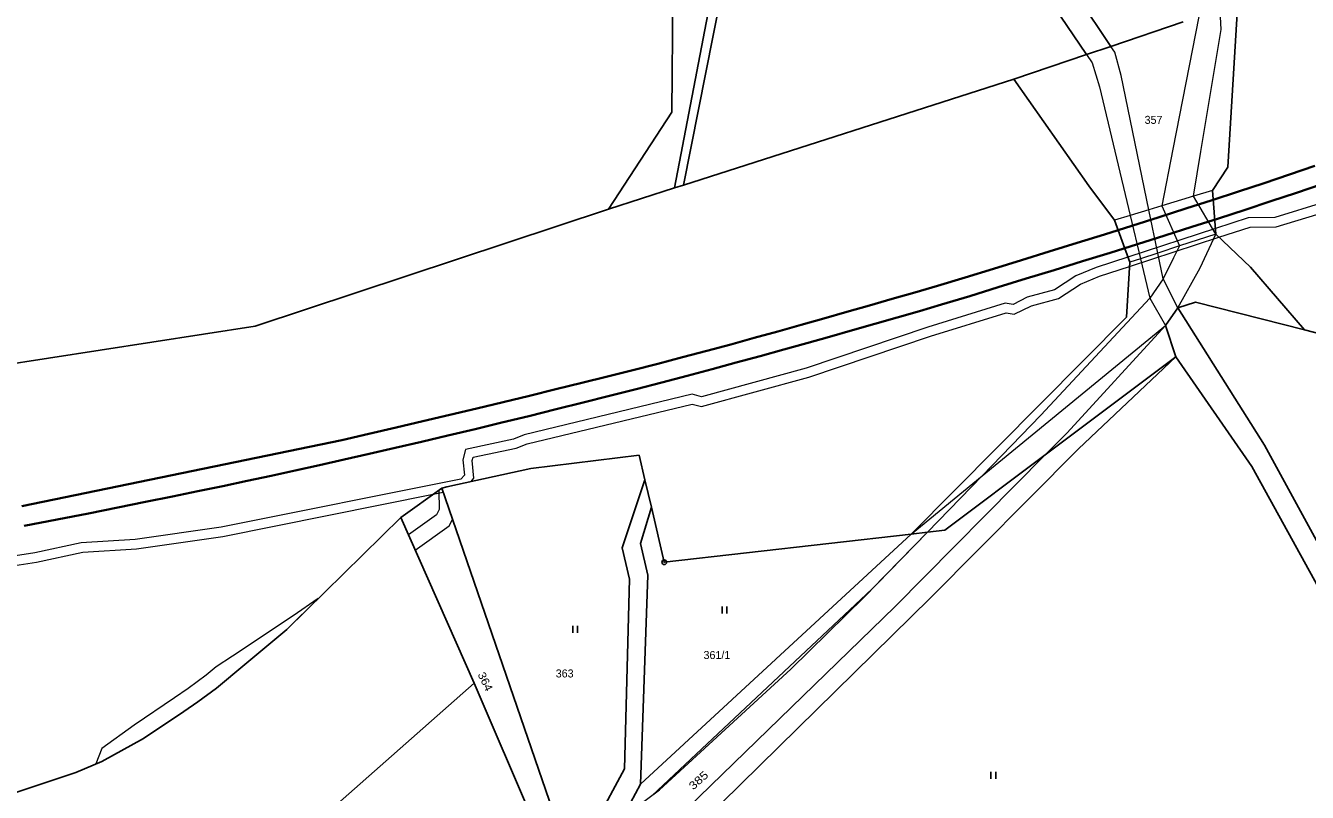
# Model space of a CAD drawing. Extents: x -504006 to -501322, y -1128098 to -1124665.
# Drawn here: x -502377.5 to -502105.3, y -1127859.7 to -1127696.8 of the extents above; entities that cross this region are included whole.
import ezdxf
from ezdxf.enums import TextEntityAlignment as Align

# ---------------------------------------------------------------- set-up
doc = ezdxf.new("R2010")
doc.units = 0
doc.header["$LTSCALE"] = 0.68
for name, color, linetype, lineweight in [('1', 7, 'Continuous', 25), ('13', 7, 'Continuous', 13), ('3', 7, 'Continuous', 25), ('4', 7, 'Continuous', 13), ('6', 7, 'Continuous', 25), ('8', 7, 'Continuous', 25)]:
    doc.layers.add(name, color=color, linetype=linetype, lineweight=lineweight)
doc.layers.add('2', color=7, linetype='Continuous')

msp = doc.modelspace()

# ---------------------------------------------------------------- linework, layer by layer
at = {"layer": '1'}
for p, q in [((-502239.63, -1127731.27), (-502230.12, -1127681.52)), ((-502237.75, -1127730.67), (-502228.06, -1127681.7)), ((-502122.15, -1127726.85), (-502119.34, -1127680.7)), ((-502239.91, -1127683.32), (-502240.23, -1127715.16)), ((-502155.42, -1127688.46), (-502147.02, -1127701.19)), ((-502159.02, -1127692.78), (-502152.15, -1127702.92)), ((-502131.6, -1127695.98), (-502147.02, -1127701.19)), ((-502147.02, -1127701.19), (-502152.15, -1127702.92)), ((-502152.15, -1127702.92), (-502167.6, -1127708.14)), ((-502167.6, -1127708.14), (-502237.75, -1127730.67)), ((-502151.69, -1127730.82), (-502167.6, -1127708.14)), ((-502240.23, -1127715.16), (-502253.68, -1127735.78)), ((-502125.4, -1127731.8), (-502122.15, -1127726.85)), ((-502237.75, -1127730.67), (-502239.63, -1127731.27)), ((-502146.21, -1127738.13), (-502151.69, -1127730.82)), ((-502239.63, -1127731.27), (-502253.68, -1127735.78)), ((-502124.69, -1127741.11), (-502125.4, -1127731.8)), ((-502253.68, -1127735.78), (-502328.73, -1127760.63)), ((-502142.97, -1127747.04), (-502146.21, -1127738.13)), ((-502117.3, -1127748.12), (-502124.69, -1127741.11)), ((-502143.69, -1127758.75), (-502142.97, -1127747.04)), ((-502105.88, -1127761.39), (-502117.3, -1127748.12)), ((-502129, -1127755.51), (-502132.79, -1127756.71)), ((-502105.88, -1127761.39), (-502129, -1127755.51)), ((-502132.79, -1127756.71), (-502135.4, -1127760.46)), ((-502114.36, -1127785.92), (-502132.79, -1127756.71)), ((-502328.73, -1127760.63), (-502398.49, -1127771.47)), ((-502189.39, -1127804.79), (-502143.69, -1127758.75)), ((-502133.18, -1127767.18), (-502135.4, -1127760.46)), ((-502063.81, -1127772.4), (-502105.88, -1127761.39)), ((-502133.18, -1127767.18), (-502160.93, -1127787.99)), ((-502153.83, -1127786.72), (-502133.18, -1127767.18)), ((-502117.07, -1127790.47), (-502133.18, -1127767.18)), ((-502247.15, -1127788), (-502270.18, -1127790.9)), ((-502245.93, -1127793.26), (-502247.15, -1127788)), ((-502185.36, -1127818.43), (-502153.83, -1127786.72)), ((-502160.93, -1127787.99), (-502182.24, -1127803.97)), ((-502087.43, -1127835.38), (-502114.36, -1127785.92)), ((-502270.18, -1127790.9), (-502288.01, -1127794.74)), ((-502090.95, -1127837.87), (-502117.07, -1127790.47)), ((-502250.77, -1127807.74), (-502245.93, -1127793.26)), ((-502244.56, -1127799.1), (-502245.93, -1127793.26)), ((-502289.09, -1127795.08), (-502297.8, -1127801.25)), ((-502288.01, -1127794.74), (-502289.09, -1127795.08)), ((-502261.45, -1127875.35), (-502289.09, -1127795.08)), ((-502246.87, -1127806.83), (-502244.56, -1127799.1)), ((-502241.84, -1127810.79), (-502244.56, -1127799.1)), ((-502297.8, -1127801.25), (-502322.01, -1127825.1)), ((-502282.17, -1127836.5), (-502297.8, -1127801.25)), ((-502185.96, -1127804.4), (-502189.39, -1127804.79)), ((-502182.24, -1127803.97), (-502185.96, -1127804.4)), ((-502189.39, -1127804.79), (-502246.89, -1127857.93)), ((-502245.31, -1127813.55), (-502246.87, -1127806.83)), ((-502189.39, -1127804.79), (-502241.84, -1127810.79)), ((-502249.22, -1127814.36), (-502250.77, -1127807.74)), ((-502250.3, -1127854.66), (-502249.22, -1127814.36)), ((-502246.89, -1127857.93), (-502245.31, -1127813.55)), ((-502243.76, -1127875.74), (-502185.36, -1127818.43)), ((-502322.01, -1127825.1), (-502330.89, -1127832.47)), ((-502330.89, -1127832.47), (-502336.96, -1127837.54)), ((-502339.14, -1127886.6), (-502282.17, -1127836.5)), ((-502263.24, -1127880.61), (-502282.17, -1127836.5)), ((-502336.96, -1127837.54), (-502340.92, -1127840.43)), ((-502343.88, -1127842.47), (-502352.4, -1127848.23)), ((-502340.92, -1127840.43), (-502343.88, -1127842.47)), ((-502352.4, -1127848.23), (-502361.27, -1127853.1)), ((-502361.27, -1127853.1), (-502366.78, -1127855.42)), ((-502366.78, -1127855.42), (-502389.61, -1127863.03)), ((-502261.45, -1127875.35), (-502250.3, -1127854.66)), ((-502246.89, -1127857.93), (-502268.68, -1127898.79))]:
    msp.add_line(p, q, dxfattribs=at)
at = {"layer": '13'}
for points in [[(-502101.61, -1127734.31), (-502112.19, -1127737.55), (-502117.86, -1127737.62), (-502124.78, -1127739.88), (-502143.36, -1127745.96), (-502150.13, -1127748.17), (-502154.4, -1127749.94), (-502158.98, -1127752.93), (-502164.74, -1127754.5), (-502167.72, -1127756.01), (-502169.45, -1127755.72), (-502185.89, -1127760.83), (-502211.72, -1127769.54), (-502233.96, -1127775.67), (-502235.94, -1127775.11), (-502271.58, -1127783.71), (-502273.86, -1127784.67), (-502284.07, -1127786.84), (-502284.61, -1127789.05), (-502284.29, -1127792.28), (-502285.07, -1127793.15), (-502335.96, -1127803.33), (-502354.19, -1127805.98), (-502365.64, -1127806.68), (-502375.54, -1127808.78), (-502388.4, -1127810.75)], [(-502388.09, -1127812.72), (-502375.12, -1127810.74), (-502365.3, -1127808.66), (-502353.9, -1127807.96), (-502335.59, -1127805.3), (-502290.88, -1127796.35), (-502288.8, -1127795.93), (-502289.09, -1127795.08), (-502288.01, -1127794.74), (-502286.24, -1127794.36), (-502282.87, -1127793.63), (-502282.27, -1127792.91), (-502282.6, -1127789.2), (-502282.42, -1127788.45), (-502273.27, -1127786.58), (-502270.97, -1127785.62), (-502235.94, -1127777.17), (-502233.92, -1127777.73), (-502211.15, -1127771.46), (-502185.29, -1127762.74), (-502169.23, -1127757.78), (-502167.54, -1127758.06), (-502163.86, -1127756.3), (-502158.14, -1127754.78), (-502153.45, -1127751.71), (-502149.4, -1127750.03), (-502143.03, -1127747.95), (-502124.03, -1127741.74), (-502117.4, -1127739.57), (-502111.87, -1127739.55), (-502100.91, -1127736.19)]]:
    msp.add_lwpolyline(points, dxfattribs=at)
for points in [[(-502286.81, -1127801.7), (-502288.8, -1127795.93), (-502289.09, -1127795.08), (-502289.72, -1127795.53), (-502289.65, -1127799.55), (-502290.22, -1127800.72), (-502296.17, -1127804.93), (-502294.72, -1127808.19), (-502287.48, -1127803.06)], [(-502189.39, -1127804.79), (-502246.89, -1127857.93), (-502250.58, -1127864.85), (-502242.85, -1127859.14), (-502214.94, -1127833.48), (-502199.31, -1127818.14), (-502185.96, -1127804.4)], [(-502320.64, -1127822.14), (-502333.56, -1127830.7), (-502337.02, -1127833.03), (-502339.12, -1127834.78), (-502342.95, -1127837.58), (-502345.85, -1127839.58), (-502354.41, -1127845.36), (-502361.3, -1127850.36), (-502362.52, -1127853.63), (-502361.27, -1127853.1), (-502352.4, -1127848.23), (-502343.88, -1127842.47), (-502340.92, -1127840.43), (-502336.96, -1127837.54), (-502334.92, -1127835.83), (-502330.89, -1127832.47), (-502322.01, -1127825.1), (-502315.32, -1127818.51)]]:
    msp.add_lwpolyline(points, close=True, dxfattribs=at)
at = {"layer": '3'}
for p, q in [((-502229.551, -1127821.68), (-502229.551, -1127820.18)), ((-502228.55, -1127821.68), (-502228.55, -1127820.18)), ((-502261.231, -1127825.79), (-502261.231, -1127824.29)), ((-502260.23, -1127825.79), (-502260.23, -1127824.29)), ((-502172.451, -1127856.79), (-502172.451, -1127855.29)), ((-502171.45, -1127856.79), (-502171.45, -1127855.29))]:
    msp.add_line(p, q, dxfattribs=at)
at = {"layer": '4'}
for p, q in [((-502123.56, -1127697.6), (-502124.56, -1127680.07)), ((-502128.32, -1127694.87), (-502133.82, -1127723.04)), ((-502127.88, -1127723.54), (-502123.56, -1127697.6)), ((-502146.18, -1127702.46), (-502147.02, -1127701.19)), ((-502152.15, -1127702.92), (-502150.98, -1127704.66)), ((-502144.81, -1127707.38), (-502146.18, -1127702.46)), ((-502150.98, -1127704.66), (-502149.4, -1127709.77)), ((-502138.93, -1127735.92), (-502144.81, -1127707.38)), ((-502149.4, -1127709.77), (-502142.88, -1127737.12)), ((-502133.82, -1127723.04), (-502136.18, -1127735.08)), ((-502129.46, -1127733.04), (-502127.88, -1127723.54)), ((-502129.46, -1127733.04), (-502136.18, -1127735.08)), ((-502125.4, -1127731.8), (-502129.46, -1127733.04)), ((-502124.69, -1127741.11), (-502129.46, -1127733.04)), ((-502138.93, -1127735.92), (-502142.88, -1127737.12)), ((-502136.18, -1127735.08), (-502138.93, -1127735.92)), ((-502137.03, -1127745.11), (-502138.93, -1127735.92)), ((-502136.18, -1127735.08), (-502132.38, -1127743.6)), ((-502142.88, -1127737.12), (-502146.21, -1127738.13)), ((-502142.88, -1127737.12), (-502140.69, -1127746.3)), ((-502124.69, -1127741.11), (-502132.38, -1127743.6)), ((-502128.05, -1127748.24), (-502124.69, -1127741.11)), ((-502132.38, -1127743.6), (-502137.03, -1127745.11)), ((-502132.38, -1127743.6), (-502133.66, -1127746.15)), ((-502140.69, -1127746.3), (-502142.97, -1127747.04)), ((-502137.03, -1127745.11), (-502140.69, -1127746.3)), ((-502140.69, -1127746.3), (-502138.68, -1127754.71)), ((-502135.9, -1127750.59), (-502137.03, -1127745.11)), ((-502133.66, -1127746.15), (-502135.9, -1127750.59)), ((-502132.79, -1127756.71), (-502128.05, -1127748.24)), ((-502135.9, -1127750.59), (-502138.68, -1127754.71)), ((-502132.79, -1127756.71), (-502135.9, -1127750.59)), ((-502161.84, -1127779.57), (-502138.68, -1127754.71)), ((-502138.68, -1127754.71), (-502135.4, -1127760.46)), ((-502174.33, -1127792.42), (-502135.4, -1127760.46)), ((-502135.4, -1127760.46), (-502156.24, -1127783.26)), ((-502174.33, -1127792.42), (-502161.84, -1127779.57)), ((-502156.24, -1127783.26), (-502160.93, -1127787.99)), ((-502160.93, -1127787.99), (-502192.89, -1127820.22)), ((-502189.39, -1127804.79), (-502174.33, -1127792.42)), ((-502185.96, -1127804.4), (-502174.33, -1127792.42)), ((-502197.74, -1127816.52), (-502185.96, -1127804.4)), ((-502244.4, -1127860.31), (-502197.74, -1127816.52)), ((-502192.89, -1127820.22), (-502239.3, -1127865.39))]:
    msp.add_line(p, q, dxfattribs=at)
at = {"layer": '6', "lineweight": 35}
msp.add_line((-502378.27, -1127798.87), (-502310.33, -1127784.83), dxfattribs=at)
for points in [[(-502183.84, -1127752.08), (-502177.906, -1127750.261), (-502171.908, -1127748.421), (-502165.996, -1127746.603), (-502160.106, -1127744.785), (-502154.174, -1127742.946), (-502148.348, -1127741.13), (-502142.566, -1127739.315), (-502136.765, -1127737.48), (-502131.091, -1127735.668), (-502125.481, -1127733.857), (-502119.878, -1127732.027), (-502114.42, -1127730.22), (-502109.045, -1127728.415), (-502103.676, -1127726.585)], [(-502102.186, -1127730.462), (-502107.589, -1127732.287), (-502113, -1127734.09), (-502118.495, -1127735.897), (-502124.138, -1127737.73), (-502129.787, -1127739.545), (-502135.502, -1127741.364), (-502141.345, -1127743.208), (-502147.17, -1127745.032), (-502153.039, -1127746.859), (-502159.016, -1127748.71), (-502164.951, -1127750.541), (-502170.908, -1127752.373), (-502176.951, -1127754.227), (-502182.93, -1127756.06)], [(-502310.33, -1127784.83), (-502304.598, -1127783.49), (-502298.804, -1127782.134), (-502293.092, -1127780.793), (-502287.401, -1127779.452), (-502281.668, -1127778.093), (-502276.037, -1127776.749), (-502270.446, -1127775.404), (-502264.835, -1127774.04), (-502259.345, -1127772.69), (-502253.915, -1127771.338), (-502248.488, -1127769.968), (-502243.2, -1127768.61), (-502237.99, -1127767.249), (-502232.792, -1127765.869), (-502227.723, -1127764.503), (-502222.714, -1127763.134), (-502217.699, -1127761.747), (-502212.792, -1127760.374), (-502207.924, -1127759), (-502203.032, -1127757.607), (-502198.225, -1127756.231), (-502193.438, -1127754.853), (-502188.607, -1127753.458), (-502183.84, -1127752.08)], [(-502182.93, -1127756.06), (-502187.625, -1127757.411), (-502192.387, -1127758.779), (-502197.112, -1127760.133), (-502201.867, -1127761.489), (-502206.719, -1127762.865), (-502211.563, -1127764.229), (-502216.467, -1127765.599), (-502221.5, -1127766.991), (-502226.553, -1127768.374), (-502231.695, -1127769.764), (-502236.999, -1127771.181), (-502242.35, -1127772.59), (-502247.814, -1127774.009), (-502253.443, -1127775.451), (-502259.081, -1127776.876), (-502264.772, -1127778.297), (-502270.564, -1127779.727), (-502276.298, -1127781.126), (-502282.02, -1127782.506), (-502287.777, -1127783.879), (-502293.411, -1127785.208), (-502298.968, -1127786.503), (-502304.492, -1127787.776), (-502309.83, -1127788.99), (-502315.038, -1127790.159), (-502320.217, -1127791.306), (-502325.294, -1127792.413), (-502330.381, -1127793.505), (-502335.592, -1127794.607), (-502340.854, -1127795.703), (-502346.279, -1127796.817), (-502351.987, -1127797.975), (-502357.892, -1127799.159), (-502364.113, -1127800.394), (-502370.782, -1127801.708), (-502377.79, -1127803.08)]]:
    msp.add_lwpolyline(points, dxfattribs=at)
at = {"layer": '8'}
for radius in [0.5, 0.0303]:
    msp.add_circle((-502241.84, -1127810.7899), radius, dxfattribs=at)

# ---------------------------------------------------------------- texts
at = {"layer": '2'}
for s, p in [('357', (-502137.929, -1127717.655)), ('361/1', (-502230.65, -1127831.335)), ('363', (-502262.989, -1127835.255))]:
    msp.add_text(s, height=1.7, dxfattribs=at).set_placement(p, align=Align.CENTER)
for s, rotation, width, p in [('364', 296, 1.1, (-502280.5985, -1127836.4954)), ('385', 42, 1.2, (-502233.9953, -1127857.745))]:
    msp.add_text(s, height=1.7, rotation=rotation, dxfattribs=dict(at, width=width)).set_placement(p, align=Align.CENTER)

doc.saveas('drawing.dxf')
